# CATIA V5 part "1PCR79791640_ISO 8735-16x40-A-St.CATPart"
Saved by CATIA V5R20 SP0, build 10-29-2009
Part number: 1PCR79791640_ISO 8735-16x40-A-St
Revision: ANY
Definition: UNKNOWN
Nomenclature: 1PCR79791640_ISO 8735-16x40-A-St
Source: Unknown
Bounding box of the stored display mesh (mm): x 0 to 40, y -8 to 8, z -8 to 8
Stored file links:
  C:\Users\Utente\Desktop\IO LAVORO\3D X SITO CF\CUMSA\3D files RC\RC 328012\1PCR79791640_ISO 8735-16x40-A-St.CATPart
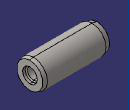
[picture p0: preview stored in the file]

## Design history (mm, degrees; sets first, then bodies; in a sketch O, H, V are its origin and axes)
Body1 "TypeA" (main body)
  Solid1: solid without history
